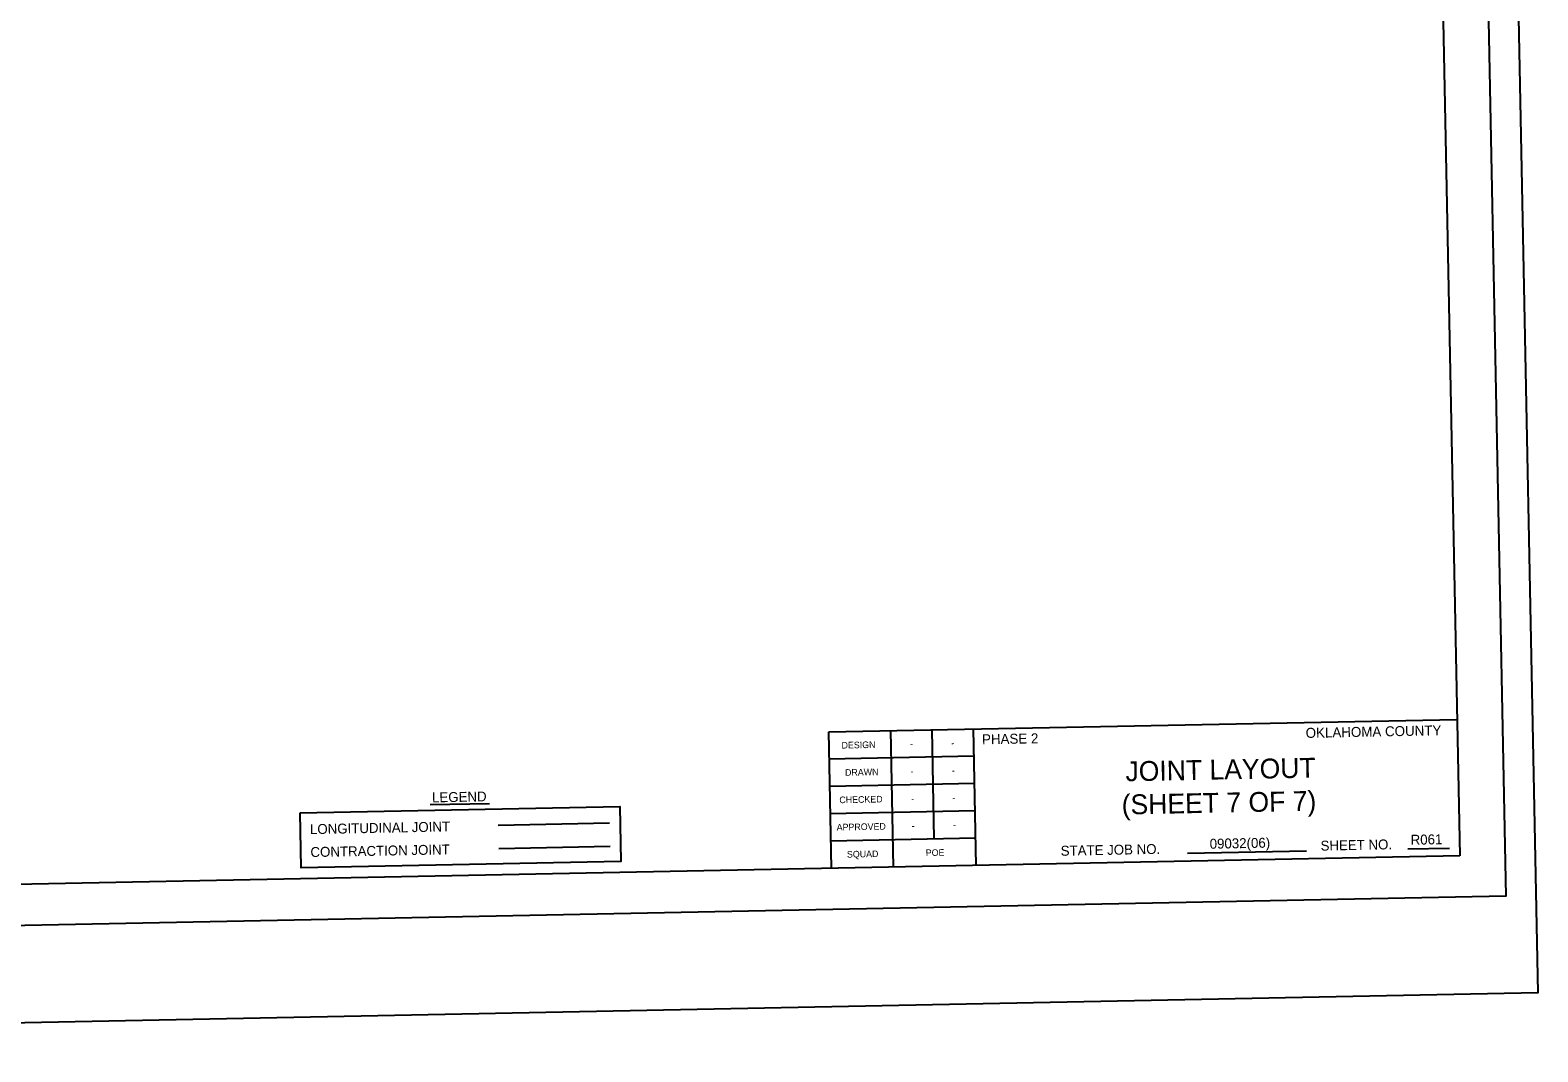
# Model space of a CAD drawing. Extents: x 2150263 to 2151357, y 141764 to 142505.
# Drawn here: x 2150810 to 2151357, y 141764 to 142134 of the extents above; entities that cross this region are included whole.
import ezdxf

# ---------------------------------------------------------------- set-up
doc = ezdxf.new("R2010")
doc.units = 0
for name, color, linetype in [('PR_Align_1_PI_Curve', 7, 'Continuous'), ('PR_Align_4', 7, 'Continuous'), ('PR_Align_4_Sta', 7, 'Continuous'), ('PR_Align_Ramp_A_PI_Curve', 7, 'Continuous'), ('PR_Align_Ramp_G_Leader', 7, 'Continuous'), ('PR_Align_Ramp_G_Txt', 7, 'Continuous'), ('PR_Align_Ramp_L_Txt', 7, 'Continuous'), ('PR_Align_Service_B_PC', 7, 'Continuous')]:
    doc.layers.add(name, color=color, linetype=linetype)

msp = doc.modelspace()

# ---------------------------------------------------------------- linework, layer by layer
at = {"layer": 'PR_Align_1_PI_Curve'}
msp.add_line((2150955.3, 141853.47), (2150976.9, 141853.89), dxfattribs=at)
msp.add_lwpolyline([(2150908.15, 141850.46), (2151024.14, 141852.76), (2151024.53, 141832.81), (2150908.54, 141830.51)], close=True, dxfattribs=at)
at = {"layer": 'PR_Align_4'}
for p, q in [((2151123.42, 141830.81), (2151122.44, 141880.33)), ((2151138.22, 141841.02), (2151137.43, 141880.63)), ((2151230.16, 141835.82), (2151273.36, 141836.67)), ((2151310.09, 141837.4), (2151325.16, 141837.7))]:
    msp.add_line(p, q, dxfattribs=at)
for points in [[(2151152.63, 141871), (2151100.14, 141869.96)], [(2151152.82, 141861.1), (2151100.34, 141860.06)], [(2151153.02, 141851.21), (2151100.53, 141850.17)], [(2151153.22, 141841.31), (2151100.73, 141840.27)]]:
    msp.add_lwpolyline(points, dxfattribs=at)
at = {"layer": 'PR_Align_Ramp_A_PI_Curve'}
msp.add_lwpolyline([(2150312.8, 142459.88), (2151332.6, 142480.09), (2151345.67, 141820.22), (2150325.87, 141800.01)], close=True, dxfattribs=at)
at = {"layer": 'PR_Align_Ramp_G_Leader'}
msp.add_lwpolyline([(2150263.19, 142483.65), (2151342.98, 142505.05), (2151357.24, 141785.19), (2150277.46, 141763.79)], close=True, dxfattribs=at)
at = {"layer": 'PR_Align_Ramp_G_Txt'}
for p, q in [((2151099.94, 141879.86), (2151327.9, 141884.38)), ((2151100.92, 141830.37), (2151099.94, 141879.86)), ((2151153.41, 141831.41), (2151152.43, 141880.92))]:
    msp.add_line(p, q, dxfattribs=at)
msp.add_lwpolyline([(2151328.88, 141834.89), (2150384.06, 141816.16), (2150371.58, 142446.04), (2151316.4, 142464.76)], close=True, dxfattribs=at)
at = {"layer": 'PR_Align_Ramp_L_Txt'}
msp.add_line((2150980.05, 141846.02), (2151020.47, 141846.82), dxfattribs=at)
at = {"layer": 'PR_Align_Service_B_PC'}
msp.add_lwpolyline([(2150980.22, 141837.59), (2151020.64, 141838.39)], dxfattribs=at)

# ---------------------------------------------------------------- texts
at = {"layer": 'PR_Align_1_PI_Curve'}
for s, p in [('LEGEND', (2150956.06, 141854.27)), ('LONGITUDINAL JOINT', (2150911.78, 141842.75)), ('CONTRACTION JOINT', (2150911.95, 141834.44))]:
    msp.add_text(s, height=3.6, rotation=1.1354, dxfattribs=at).set_placement(p)
at = {"layer": 'PR_Align_4_Sta'}
for s, height, p in [('PHASE 2', 3.621, (2151155.61, 141875.33)), ('OKLAHOMA COUNTY', 3.6211, (2151273.04, 141877.66)), ('DESIGN', 2.4, (2151104.63, 141873.8)), ('-', 2.4, (2151129.47, 141874.31)), ('-', 2.4, (2151144.47, 141874.6)), ('DRAWN', 2.4, (2151105.9, 141863.92)), ('JOINT LAYOUT', 7.2, (2151207.69, 141861.92)), ('-', 2.4, (2151129.67, 141864.38)), ('-', 2.4, (2151144.67, 141864.68)), ('CHECKED', 2.4, (2151103.84, 141853.98)), ('-', 2.4, (2151129.87, 141854.49)), ('-', 2.4, (2151144.86, 141854.78)), ('(SHEET 7 OF 7)', 7.2, (2151206.31, 141849.87)), ('APPROVED', 2.4, (2151102.86, 141844.06)), ('-', 2.4, (2151130.06, 141844.59)), ('-', 2.4, (2151145.06, 141844.88)), ('STATE JOB NO.', 3.6, (2151184.16, 141834.9)), ('09032(06)', 3.6, (2151238.21, 141837.45)), ('SHEET NO. ', 3.6, (2151278.45, 141836.77)), ('R061', 3.6, (2151311.13, 141838.9)), ('SQUAD', 2.4, (2151106.59, 141834.23)), ('POE', 2.4, (2151135.19, 141834.8))]:
    msp.add_text(s, height=height, rotation=1.1354, dxfattribs=at).set_placement(p)

doc.saveas('drawing.dxf')
